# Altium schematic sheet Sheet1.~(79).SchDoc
size A
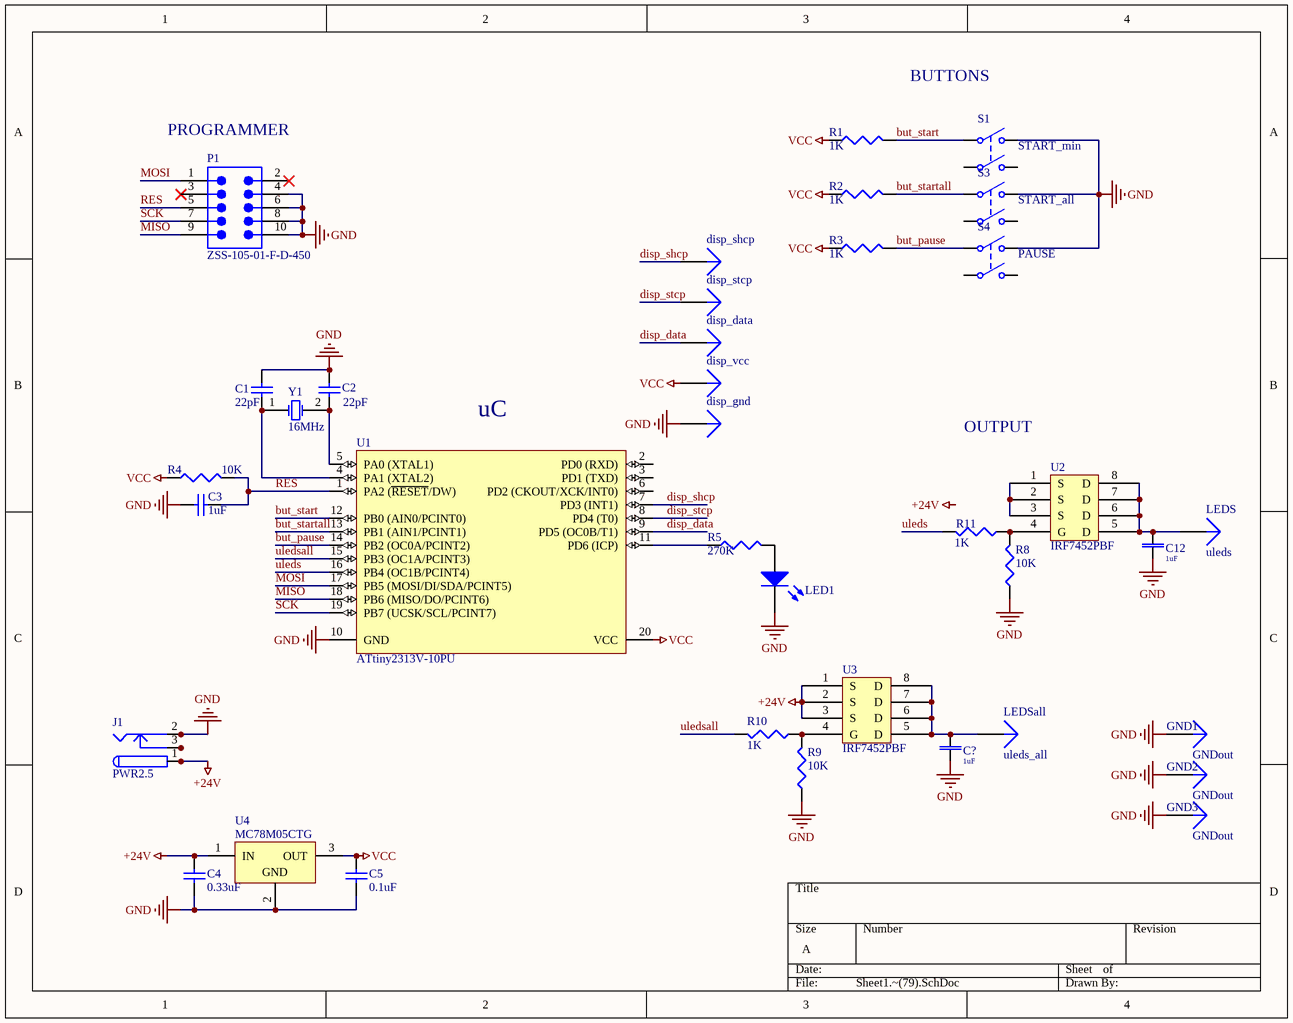
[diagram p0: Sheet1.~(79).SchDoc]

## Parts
C1  value 22pF  [CAPC1608L]  (hidden comment: Cap Semi)
C2  value 22pF  [CAPC1608L]  (hidden comment: Cap Semi)
C3  value 1uF  [CAPC1608L]  (hidden comment: Cap Semi)
C4  value 0.33uF  [CAPC1608L]  (hidden comment: Cap Semi)
C5  value 0.1uF  [CAPC1608L]  (hidden comment: Cap Semi)
C12  value 1uF  [CAPC3216L]  (hidden comment: Cap Semi)
C?  value 1uF  [CAPC3216L]  (hidden comment: Cap Semi)
disp_data  uleds_all  [PIN1]  (value not drawn)
disp_gnd  uleds_all  [PIN1]  (value not drawn)
disp_shcp  uleds_all  [PIN1]  (value not drawn)
disp_stcp  uleds_all  [PIN1]  (value not drawn)
disp_vcc  uleds_all  [PIN1]  (value not drawn)
GND1  GNDout  [PIN1]
GND2  GNDout  [PIN1]
GND3  GNDout  [PIN1]
J1  PWR2.5  [PCBComponent_1]
LED1  151051YS04000  [Type 5mm]  (value not drawn)
LEDS  uleds  [PIN1]
LEDSall  uleds_all  [PIN1]
P1  ZSS-105-01-F-D-450  [SMTC-ZSS-105-01-X-D-450]
R1  value 1K  [CAPC1608L]  (hidden comment: Res3)
R2  value 1K  [CAPC1608L]  (hidden comment: Res3)
R3  value 1K  [CAPC1608L]  (hidden comment: Res3)
R4  value 10K  [CAPC1608L]  (hidden comment: Res3)
R5  value 270K  [CAPC1608L]  (hidden comment: Res3)
R8  value 10K  [CAPC1608L]  (hidden comment: Res3)
R9  value 10K  [CAPC1608L]  (hidden comment: Res3)
R10  value 1K  [CAPC1608L]  (hidden comment: Res3)
R11  value 1K  [CAPC1608L]  (hidden comment: Res3)
S1  START_min  [key]
S3  START_all  [key]
S4  PAUSE  [key]
U1  ATtiny2313V-10PU  [20P3]
U2  IRF7452PBF  [SO-8_M]
U3  IRF7452PBF  [SO-8_M]
U4  MC78M05CTG  [TO220]
Y1  16MHz  [PCBComponent_1 - duplicate]

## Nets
+24V: C4.2 J1.1 J1.1A J1.1B U3.1(S) U3.2(S) U3.3(S) U4.1(IN)
GND: C1.1 C2.1 C3.2 C4.1 C5.1 C12.2 C?.2 disp_gnd.1 GND1.1 GND2.1 GND3.1 J1.2 J1.2A J1.2B LED1.1(K) P1.4 P1.6 P1.8 P1.10 R8.1 R9.1 S1.2(NO1) S3.2(NO1) S4.2(NO1) U1.10(GND) U4.2(GND)
VCC: C5.2 disp_vcc.1 R1.1 R2.1 R3.1 R4.1 U1.20(VCC) U4.3(OUT)
but_pause: R3.2 S4.1(COMMON1) U1.14(PB2_(OC0A/PCINT2))
but_start: R1.2 S1.1(COMMON1) U1.12(PB0_(AIN0/PCINT0))
but_startall: R2.2 S3.1(COMMON1) U1.13(PB1_(AIN1/PCINT1))
disp_data: disp_data.1 U1.9(PD5_(OC0B/T1))
disp_shcp: disp_shcp.1 U1.7(PD3_(INT1))
disp_stcp: disp_stcp.1 U1.8(PD4_(T0))
MISO: P1.9 U1.18(PB6_(MISO/DO/PCINT6))
MOSI: P1.1 U1.17(PB5_(MOSI/DI/SDA/PCINT5))
RES: C3.1 P1.5 R4.2 U1.1(PA2_(~{RESET}/DW))
SCK: P1.7 U1.19(PB7_(UCSK/SCL/PCINT7))
uleds: R11.2 U1.16(PB4_(OC1B/PCINT4))
uledsall: R10.2 U1.15(PB3_(OC1A/PCINT3))
NetC1_2: C1.2 U1.4(PA1_(XTAL2)) Y1.1(OSC1)
NetC2_2: C2.2 U1.5(PA0_(XTAL1)) Y1.2(OSC2)
NetC12_1: C12.1 LEDS.1 U2.5(D) U2.6(D) U2.7(D) U2.8(D)
NetC?_1: C?.1 LEDSall.1 U3.5(D) U3.6(D) U3.7(D) U3.8(D)
NetJ1_3: J1.3 J1.3A J1.3B
NetLED1_2: LED1.2(A) R5.2
NetR5_1: R5.1 U1.11(PD6_(ICP))
NetR8_2: R8.2 R11.1 U2.4(G)
NetR9_2: R9.2 R10.1 U3.4(G)
NetU2_1: U2.1(S) U2.2(S) U2.3(S)

Not connected (* = marked no-connect by the designer): P1 2* 3*; S1 3(COMMON2) 4(NO2); S3 3(COMMON2) 4(NO2); S4 3(COMMON2) 4(NO2); U1 2(PD0_(RXD)) 3(PD1_(TXD)) 6(PD2_(CKOUT/XCK/INT0))

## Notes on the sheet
- BUTTONS
- (near P1) PROGRAMMER
- (near U1) uC
- OUTPUT
- Labels drawn without touching a wire or pin: +24V

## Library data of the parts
C1-C5 C12 C? = Cap Semi: Capacitor (Semiconductor SIM Model)
disp_data disp_gnd disp_shcp disp_stcp disp_vcc GND1-GND3 LEDS LEDSall = Plug
J1 = PWR2.5: Low Voltage Power Supply Connector
LED1 = CMP-1488-00010-1: THT LED round mono-color color lens, WL-TMRW, Yellow; Manufacturer: Wuerth Elektronik
P1 = CMP-1024-00461-1: Manufacturer: Samtec; Pitch: 2.54 mm
R1-R5 R8-R11 = Res3: Resistor
S1 S3 S4 = SW-DPST: Double-Pole, Single-Throw Switch
U1 = CMP-0093-00017-1: Low Power tinyAVR® 8-Bit Microcontroller, 2K Flash Memory, 10MHz, Industrial Temperature, 20-Lead PDIP, Pb-Free
U4 = CMP-0244-00483-1: Positive Voltage Regulator, 5V, 3-Pin TO-220
Y1 = XTAL: Crystal Oscillator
